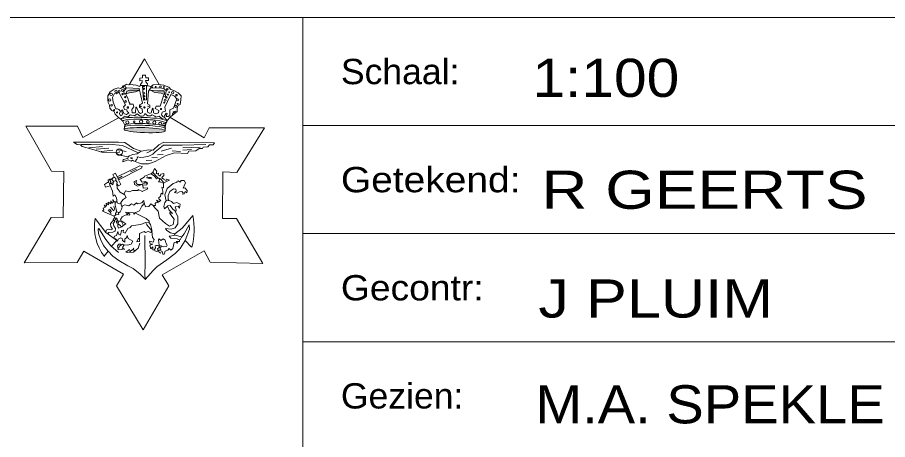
# Model space of a CAD drawing. Extents: x 295824 to 414724, y 24924 to 109024.
# Drawn here: x 402680 to 409522, y 29004 to 32324 of the extents above; entities that cross this region are included whole.
import ezdxf

# ---------------------------------------------------------------- set-up
doc = ezdxf.new("R2010")
doc.units = 0
doc.header["$LTSCALE"] = 100
doc.header["$PDMODE"] = 32
doc.header["$PDSIZE"] = 50
doc.layers.add('1', color=7, linetype='Continuous', lineweight=13)
doc.layers.add('3', color=7, linetype='Continuous')

msp = doc.modelspace()

# ---------------------------------------------------------------- hatches: boundary and pattern name
at = {"layer": '1'}
for points in [[(403531.6, 31722.8), (403540.6, 31743.8), (403560.6, 31751.8), (403641.6, 31751.8), (403609.6, 31737.8), (403557.6, 31731.8)], [(403720.6, 31751.8), (403780.6, 31745.8), (403834.6, 31745.8), (403837.6, 31716.8), (403809.6, 31727.8), (403760.6, 31733.8), (403725.6, 31750.8)]]:
    msp.add_hatch(color=256, dxfattribs=at).paths.add_polyline_path(points)
h = msp.add_hatch(color=256, dxfattribs=at)
edge = h.paths.add_edge_path()
edge.add_ellipse((403681.3, 31437.6), major_axis=(161, -5), ratio=0.122443, start_angle=0, end_angle=360)

# ---------------------------------------------------------------- linework, layer by layer
for p, q in [((395823.6, 32323.8), (413723.6, 32323.8)), ((404923.6, 32323.8), (404923.6, 28923.8)), ((403696.6, 31787.8), (403649.6, 31787.8)), ((403662.6, 31785.8), (403672.6, 31673.8)), ((403475.6, 31533.8), (403195.6, 31378.8)), ((403494.6, 31523.8), (403508.6, 31507.8)), ((403857.6, 31507.8), (403849.6, 31493.8)), ((403877.6, 31538.8), (404148.6, 31377.8)), ((404923.6, 31473.8), (413723.6, 31473.8)), ((403520.6, 31443.8), (403522.6, 31463.8)), ((403841.6, 31432.8), (403841.6, 31453.8)), ((403180.6, 31324.8), (403259.6, 31324.8)), ((403242.6, 31298.8), (403348.6, 31308.8)), ((403300.6, 31288.8), (403398.6, 31294.8)), ((403338.6, 31269.8), (403431.6, 31279.8)), ((403471.6, 31282.8), (403536.6, 31269.8)), ((403506.6, 31317.8), (403628.6, 31257.8)), ((403811.6, 31271.8), (403890.6, 31295.8)), ((403896.6, 31275.8), (403961.6, 31268.8)), ((403976.6, 31319.8), (404161.6, 31325.8)), ((403979.6, 31297.8), (404117.6, 31304.8)), ((403980.6, 31279.8), (404049.6, 31285.8)), ((403453.6, 31258.8), (403481.6, 31264.8)), ((403693.6, 31199.8), (403737.6, 31200.8)), ((403737.6, 31222.8), (403781.6, 31219.8)), ((403781.6, 31243.8), (403825.6, 31244.8)), ((403466.6, 31069.8), (403474.6, 31046.8)), ((403473.6, 31057.8), (403503.6, 31074.8)), ((403568.6, 31108.8), (403615.6, 31129.8)), ((403391.6, 31027.8), (403410.6, 31016.8)), ((403412.6, 31018.8), (403432.6, 31026.8)), ((403679.6, 31024.8), (403696.6, 31017.8)), ((403394.6, 30811.8), (403417.6, 30781.8)), ((403404.6, 30816.8), (403420.6, 30797.8)), ((403412.6, 30830.8), (403437.6, 30801.8)), ((403439.6, 30839.8), (403445.6, 30808.8)), ((403914.6, 30613.8), (403967.6, 30598.8)), ((404923.6, 30623.8), (413723.6, 30623.8)), ((403522.6, 30498.8), (403507.6, 30512.8)), ((403588.6, 30498.8), (403594.6, 30509.8)), ((404923.6, 29773.8), (413723.6, 29773.8))]:
    msp.add_line(p, q, dxfattribs=at)
for points in [[(403557.6, 31794.8), (403678.6, 31996.8), (403795.6, 31795.8)], [(403493.6, 31524.8), (403475.6, 31536.8), (403449.6, 31562.8), (403441.6, 31584.8), (403423.6, 31592.8), (403407.6, 31610.8), (403404.6, 31632.8), (403394.6, 31653.8), (403390.6, 31675.8), (403391.6, 31707.8), (403408.6, 31737.8), (403441.6, 31760.8), (403472.6, 31768.8), (403489.6, 31763.8), (403504.6, 31771.8), (403512.6, 31786.8), (403524.6, 31787.8), (403538.6, 31798.8), (403556.6, 31793.8), (403585.6, 31796.8), (403595.6, 31789.8), (403606.6, 31792.8), (403642.6, 31780.8), (403647.6, 31796.8), (403660.6, 31814.8), (403660.6, 31826.8), (403641.6, 31825.8), (403642.6, 31846.8), (403663.6, 31847.8), (403663.6, 31869.8), (403687.6, 31869.8), (403690.6, 31849.8), (403709.6, 31848.8), (403709.6, 31827.8), (403687.6, 31827.8), (403689.6, 31816.8), (403703.6, 31801.8), (403704.6, 31786.8), (403732.6, 31781.8), (403747.6, 31793.8)], [(403608.6, 31575.8), (403611.6, 31618.8), (403616.6, 31616.8), (403633.6, 31576.8), (403647.6, 31568.8), (403664.6, 31576.8), (403660.6, 31604.8), (403639.6, 31615.8), (403639.6, 31636.8), (403654.6, 31644.8), (403662.6, 31648.8), (403638.6, 31764.8), (403538.6, 31769.8), (403517.6, 31743.8), (403518.6, 31720.8), (403530.6, 31725.8), (403551.6, 31680.8), (403555.6, 31659.8), (403563.6, 31649.8), (403562.6, 31641.8), (403589.6, 31640.8), (403594.6, 31619.8), (403579.6, 31599.8), (403583.6, 31574.8), (403608.6, 31574.8)], [(403672.6, 31671.8), (403694.6, 31675.8), (403695.6, 31785.8), (403702.6, 31786.8)], [(403827.6, 31702.8), (403844.6, 31704.8), (403850.6, 31749.8), (403831.6, 31764.8), (403792.6, 31768.8), (403726.6, 31766.8), (403711.6, 31742.8), (403703.6, 31644.8), (403720.6, 31634.8), (403722.6, 31615.8), (403702.6, 31605.8), (403702.6, 31579.8), (403718.6, 31570.8)], [(403747.6, 31793.8), (403791.6, 31796.8), (403830.6, 31790.8)], [(403827.6, 31791.8), (403871.6, 31775.8), (403887.6, 31755.8), (403910.6, 31749.8), (403943.6, 31730.8), (403966.6, 31706.8), (403964.6, 31675.8), (403959.6, 31638.8), (403941.6, 31628.8), (403935.6, 31607.8), (403935.6, 31583.8), (403884.6, 31542.8), (403854.6, 31511.8)], [(403542.6, 31562.8), (403556.6, 31572.8), (403543.6, 31584.8), (403540.6, 31596.8), (403521.6, 31598.8), (403515.6, 31619.8), (403529.6, 31635.8), (403478.6, 31735.8), (403457.6, 31723.8), (403444.6, 31725.8), (403426.6, 31693.8), (403432.6, 31657.8), (403453.6, 31605.8), (403466.6, 31605.8), (403478.6, 31598.8), (403490.6, 31586.8), (403481.6, 31567.8), (403490.6, 31549.8), (403501.6, 31552.8), (403506.6, 31564.8), (403498.6, 31594.8), (403505.6, 31595.8), (403516.6, 31568.8), (403535.6, 31559.8), (403539.6, 31560.8)], [(403718.6, 31568.8), (403730.6, 31574.8), (403742.6, 31609.8), (403748.6, 31606.8), (403750.6, 31573.8), (403767.6, 31564.8), (403789.6, 31573.8), (403791.6, 31591.8), (403763.6, 31607.8), (403771.6, 31624.8), (403802.6, 31624.8), (403831.6, 31715.8)], [(403834.6, 31545.8), (403849.6, 31570.8), (403858.6, 31567.8), (403848.6, 31543.8), (403864.6, 31543.8), (403879.6, 31553.8), (403877.6, 31595.8), (403906.6, 31609.8), (403932.6, 31682.8), (403915.6, 31704.8), (403887.6, 31717.8), (403860.6, 31663.8), (403838.6, 31617.8), (403844.6, 31587.8), (403819.6, 31577.8), (403813.6, 31556.8), (403822.6, 31545.8), (403836.6, 31546.8)], [(403494.6, 31523.8), (403493.6, 31526.8), (403517.6, 31538.8), (403520.6, 31547.8), (403540.6, 31541.8), (403554.6, 31544.8), (403567.6, 31557.8), (403599.6, 31550.8), (403621.6, 31566.8), (403646.6, 31547.8), (403661.6, 31546.8), (403673.6, 31550.8), (403682.6, 31568.8), (403704.6, 31549.8), (403725.6, 31549.8), (403740.6, 31558.8), (403761.6, 31546.8), (403770.6, 31538.8), (403794.6, 31547.8), (403804.6, 31535.8), (403817.6, 31528.8), (403837.6, 31535.8), (403850.6, 31521.8), (403858.6, 31509.8)], [(403508.6, 31507.8), (403524.6, 31476.8), (403522.6, 31464.8)], [(403849.6, 31493.8), (403842.6, 31466.8), (403843.6, 31450.8)], [(403195.6, 31378.8), (403153.6, 31468.8), (402745.6, 31469.8), (402947.6, 31114.8), (403044.6, 31112.8), (403040.6, 30746.8), (402944.6, 30749.8), (402734.6, 30393.8), (403150.6, 30395.8), (403201.6, 30485.8), (403514.6, 30304.8), (403458.6, 30213.8), (403668.6, 29867.8), (403871.6, 30212.8), (403818.6, 30299.8), (404148.6, 30489.8), (404195.6, 30398.8), (404610.6, 30388.8), (404402.6, 30743.8), (404291.6, 30741.8), (404295.6, 31108.8), (404404.6, 31104.8), (404622.6, 31456.8), (404188.6, 31456.8), (404148.6, 31377.8)], [(403652.6, 31271.8), (403592.6, 31292.8), (403525.6, 31339.8), (403475.6, 31343.8), (403121.6, 31342.8), (403149.6, 31325.8), (403175.6, 31322.8), (403189.6, 31309.8), (403266.6, 31287.8), (403350.6, 31260.8), (403455.6, 31257.8), (403477.6, 31241.8), (403488.6, 31244.8), (403499.6, 31238.8), (403551.6, 31228.8), (403548.6, 31214.8), (403511.6, 31207.8), (403509.6, 31187.8), (403551.6, 31203.8)], [(403654.6, 31171.8), (403709.6, 31171.8), (403764.6, 31190.8), (403849.6, 31238.8), (403914.6, 31257.8), (404016.6, 31254.8), (404027.6, 31271.8), (404083.6, 31274.8), (404109.6, 31291.8), (404134.6, 31292.8), (404141.6, 31302.8), (404178.6, 31306.8), (404191.6, 31321.8), (404220.6, 31322.8), (404228.6, 31338.8), (403830.6, 31341.8), (403791.6, 31321.8), (403748.6, 31279.8), (403714.6, 31281.8), (403652.6, 31271.8), (403622.6, 31251.8), (403588.6, 31244.8), (403562.6, 31234.8), (403549.6, 31228.8)], [(403259.6, 31324.8), (403398.6, 31326.8), (403506.6, 31317.8)], [(403698.6, 31258.8), (403716.6, 31265.8), (403739.6, 31280.8)], [(403764.6, 31266.8), (403829.6, 31319.8), (403976.6, 31319.8)], [(403551.6, 31203.8), (403575.6, 31193.8), (403584.6, 31200.8), (403592.6, 31194.8), (403631.6, 31180.8), (403654.6, 31171.8)], [(403568.6, 31222.8), (403586.6, 31217.8), (403577.6, 31214.8), (403569.6, 31220.8)], [(403607.6, 31195.8), (403618.6, 31208.8), (403624.6, 31218.8), (403621.6, 31226.8), (403649.6, 31222.8), (403673.6, 31223.8), (403712.6, 31233.8), (403744.6, 31249.8), (403764.6, 31266.8)], [(403493.6, 30861.8), (403483.6, 30856.8), (403464.6, 30866.8), (403459.6, 30905.8), (403446.6, 30928.8), (403432.6, 30917.8), (403426.6, 30957.8), (403408.6, 31000.8), (403372.6, 30989.8), (403365.6, 31008.8), (403395.6, 31031.8), (403394.6, 31043.8), (403406.6, 31050.8), (403427.6, 31056.8), (403432.6, 31063.8), (403441.6, 31066.8), (403431.6, 31089.8), (403450.6, 31098.8), (403465.6, 31070.8), (403642.6, 31155.8), (403660.6, 31152.8), (403654.6, 31137.8), (403474.6, 31046.8), (403493.6, 31010.8), (403474.6, 30999.8), (403462.6, 31014.8), (403464.6, 31027.8), (403454.6, 31040.8), (403454.6, 31057.8), (403440.6, 31068.8)], [(403661.6, 30955.8), (403705.6, 30974.8), (403700.6, 30984.8), (403669.6, 30981.8), (403665.6, 31005.8), (403697.6, 31007.8), (403702.6, 31021.8), (403688.6, 31033.8), (403660.6, 31027.8), (403644.6, 31048.8), (403677.6, 31066.8), (403679.6, 31076.8), (403733.6, 31097.8), (403747.6, 31109.8), (403757.6, 31134.8), (403775.6, 31113.8), (403771.6, 31097.8), (403779.6, 31096.8), (403790.6, 31099.8), (403787.6, 31084.8), (403801.6, 31074.8), (403806.6, 31090.8), (403830.6, 31097.8), (403832.6, 31079.8), (403814.6, 31064.8), (403820.6, 31056.8), (403832.6, 31054.8), (403832.6, 31048.8), (403848.6, 31041.8), (403855.6, 31052.8), (403876.6, 31043.8), (403851.6, 31032.8), (403827.6, 31020.8), (403827.6, 30998.8), (403827.6, 30984.8), (403814.6, 30987.8), (403824.6, 30957.8), (403823.6, 30933.8), (403810.6, 30941.8), (403804.6, 30915.8)], [(403701.6, 31069.8), (403713.6, 31063.8), (403730.6, 31064.8), (403730.6, 31055.8), (403717.6, 31056.8), (403697.6, 31062.8), (403700.6, 31070.8)], [(403732.6, 31094.8), (403757.6, 31074.8), (403773.6, 31053.8), (403792.6, 31058.8), (403800.6, 31049.8), (403790.6, 31029.8), (403801.6, 31029.8), (403825.6, 31020.8)], [(403745.6, 31103.8), (403782.6, 31063.8), (403804.6, 31053.8), (403826.6, 31031.8), (403827.6, 31024.8)], [(403453.6, 31041.8), (403436.6, 31033.8), (403430.6, 31007.8), (403415.6, 31020.8), (403403.6, 31014.8), (403409.6, 31001.8)], [(403410.6, 31019.8), (403415.6, 31030.8), (403405.6, 31043.8), (403422.6, 31051.8), (403434.6, 31034.8)], [(403519.6, 30930.8), (403488.6, 30949.8), (403464.6, 30980.8), (403462.6, 31014.8)], [(403667.6, 31003.8), (403658.6, 31008.8), (403623.6, 30997.8), (403599.6, 31008.8), (403597.6, 31033.8), (403619.6, 31041.8), (403612.6, 31026.8), (403623.6, 31009.8), (403653.6, 31010.8), (403679.6, 31019.8), (403676.6, 31029.8)], [(403871.6, 30883.8), (403849.6, 30880.8), (403839.6, 30928.8), (403857.6, 30979.8), (403903.6, 31017.8), (403935.6, 31027.8), (403933.6, 31034.8), (403943.6, 31038.8), (403959.6, 31027.8), (403965.6, 31035.8), (403964.6, 31041.8), (403990.6, 31041.8), (404001.6, 31023.8), (403992.6, 31000.8), (403982.6, 30980.8), (403995.6, 30982.8), (404015.6, 30963.8), (404012.6, 30944.8), (403998.6, 30954.8), (403990.6, 30937.8), (403977.6, 30932.8), (403982.6, 30943.8), (403973.6, 30954.8), (403954.6, 30952.8), (403935.6, 30941.8), (403916.6, 30947.8), (403929.6, 30958.8), (403924.6, 30973.8), (403907.6, 30975.8), (403878.6, 30954.8), (403864.6, 30922.8), (403865.6, 30891.8), (403870.6, 30883.8)], [(403804.6, 30915.8), (403792.6, 30908.8), (403791.6, 30897.8), (403799.6, 30888.8), (403808.6, 30886.8), (403794.6, 30874.8), (403787.6, 30877.8), (403774.6, 30887.8), (403782.6, 30876.8), (403786.6, 30865.8), (403771.6, 30867.8), (403762.6, 30859.8), (403766.6, 30845.8), (403747.6, 30844.8), (403728.6, 30858.8), (403714.6, 30837.8), (403688.6, 30833.8), (403676.6, 30862.8), (403674.6, 30884.8), (403658.6, 30866.8), (403625.6, 30858.8), (403617.6, 30865.8), (403594.6, 30846.8), (403576.6, 30856.8), (403555.6, 30841.8), (403525.6, 30849.8), (403497.6, 30839.8), (403493.6, 30869.8), (403512.6, 30892.8), (403534.6, 30906.8), (403520.6, 30935.8), (403529.6, 30960.8), (403561.6, 30951.8), (403585.6, 30962.8), (403617.6, 30961.8), (403628.6, 30963.8), (403628.6, 30970.8), (403663.6, 30955.8)], [(403461.6, 30794.8), (403447.6, 30848.8), (403449.6, 30867.8), (403458.6, 30874.8), (403441.6, 30874.8), (403431.6, 30890.8), (403433.6, 30871.8), (403425.6, 30863.8), (403413.6, 30881.8), (403415.6, 30856.8), (403394.6, 30871.8), (403396.6, 30850.8), (403377.6, 30863.8), (403379.6, 30840.8), (403363.6, 30848.8), (403373.6, 30831.8), (403353.6, 30823.8), (403360.6, 30810.8), (403348.6, 30800.8), (403367.6, 30793.8), (403441.6, 30760.8)], [(403531.6, 30701.8), (403509.6, 30683.8), (403500.6, 30676.8), (403475.6, 30666.8), (403470.6, 30678.8), (403469.6, 30701.8), (403491.6, 30687.8), (403493.6, 30680.8), (403506.6, 30682.8), (403512.6, 30693.8), (403491.6, 30735.8), (403502.6, 30755.8), (403528.6, 30769.8), (403548.6, 30772.8), (403560.6, 30767.8), (403563.6, 30775.8), (403554.6, 30785.8), (403541.6, 30773.8), (403540.6, 30789.8), (403526.6, 30793.8), (403592.6, 30786.8), (403598.6, 30774.8), (403602.6, 30789.8), (403616.6, 30793.8), (403640.6, 30803.8), (403657.6, 30840.8), (403678.6, 30863.8)], [(403748.6, 30844.8), (403759.6, 30827.8), (403785.6, 30799.8), (403797.6, 30745.8), (403844.6, 30703.8), (403875.6, 30682.8), (403904.6, 30694.8), (403913.6, 30737.8), (403877.6, 30780.8), (403877.6, 30790.8), (403898.6, 30780.8), (403874.6, 30807.8), (403861.6, 30840.8), (403836.6, 30818.8), (403832.6, 30836.8), (403839.6, 30869.8), (403850.6, 30881.8)], [(403872.6, 30884.8), (403892.6, 30875.8), (403908.6, 30860.8), (403934.6, 30867.8), (403959.6, 30855.8), (403955.6, 30824.8), (403944.6, 30838.8), (403921.6, 30833.8), (403928.6, 30809.8), (403924.6, 30796.8), (403901.6, 30814.8), (403880.6, 30845.8), (403860.6, 30841.8)], [(403506.6, 30841.8), (403498.6, 30815.8), (403488.6, 30795.8), (403475.6, 30785.8), (403478.6, 30774.8), (403454.6, 30771.8), (403441.6, 30761.8), (403442.6, 30747.8), (403445.6, 30744.8), (403437.6, 30744.8), (403433.6, 30732.8), (403437.6, 30728.8), (403427.6, 30722.8), (403411.6, 30699.8), (403414.6, 30678.8), (403426.6, 30658.8), (403416.6, 30653.8), (403397.6, 30658.8), (403377.6, 30649.8), (403375.6, 30632.8), (403392.6, 30623.8), (403399.6, 30632.8), (403429.6, 30635.8), (403449.6, 30643.8), (403451.6, 30662.8), (403439.6, 30685.8), (403433.6, 30703.8), (403443.6, 30717.8), (403444.6, 30727.8), (403452.6, 30733.8), (403459.6, 30740.8), (403446.6, 30748.8), (403461.6, 30744.8), (403466.6, 30726.8), (403456.6, 30719.8), (403465.6, 30705.8), (403474.6, 30708.8), (403468.6, 30721.8), (403501.6, 30720.8), (403531.6, 30701.8)], [(403477.6, 30788.8), (403460.6, 30795.8), (403450.6, 30781.8), (403452.6, 30773.8)], [(403922.6, 30794.8), (403942.6, 30754.8), (403942.6, 30699.8), (403921.6, 30669.8), (403889.6, 30659.8), (403844.6, 30664.8), (403855.6, 30648.8), (403882.6, 30629.8), (403917.6, 30622.8), (403975.6, 30666.8), (404034.6, 30736.8), (404058.6, 30765.8)], [(403416.6, 30522.8), (403462.6, 30570.8), (403374.6, 30632.8), (403292.6, 30741.8)], [(403603.6, 30787.8), (403644.6, 30766.8), (403692.6, 30741.8), (403715.6, 30722.8), (403716.6, 30708.8), (403687.6, 30711.8), (403649.6, 30696.8), (403591.6, 30688.8), (403576.6, 30685.8), (403567.6, 30671.8)], [(403475.6, 30475.8), (403413.6, 30526.8), (403375.6, 30576.8), (403319.6, 30664.8), (403315.6, 30659.8), (403316.6, 30623.8), (403334.6, 30580.8), (403357.6, 30530.8), (403390.6, 30488.8)], [(403567.6, 30672.8), (403547.6, 30662.8), (403528.6, 30627.8), (403512.6, 30634.8), (403513.6, 30651.8), (403498.6, 30647.8), (403489.6, 30612.8), (403474.6, 30619.8), (403470.6, 30639.8), (403460.6, 30609.8), (403442.6, 30602.8), (403438.6, 30586.8), (403450.6, 30583.8), (403466.6, 30564.8), (403471.6, 30580.8), (403492.6, 30590.8), (403502.6, 30585.8), (403506.6, 30569.8), (403524.6, 30556.8), (403524.6, 30581.8), (403537.6, 30591.8), (403543.6, 30609.8), (403550.6, 30585.8), (403586.6, 30564.8), (403575.6, 30540.8), (403545.6, 30532.8), (403520.6, 30535.8), (403506.6, 30514.8)], [(403689.6, 30709.8), (403698.6, 30691.8), (403737.6, 30644.8), (403728.6, 30632.8), (403707.6, 30641.8), (403688.6, 30633.8), (403676.6, 30640.8), (403640.6, 30624.8), (403639.6, 30590.8), (403639.6, 30561.8), (403618.6, 30559.8), (403631.6, 30586.8)], [(403715.6, 30708.8), (403726.6, 30694.8), (403733.6, 30664.8), (403738.6, 30643.8)], [(404049.6, 30516.8), (403999.6, 30569.8), (404032.6, 30659.8), (404029.6, 30692.8), (403990.6, 30622.8), (403969.6, 30594.8), (403958.6, 30574.8)], [(403999.6, 30569.8), (403960.6, 30506.8), (403921.6, 30467.8), (403855.6, 30418.8), (403777.6, 30361.8), (403748.6, 30332.8), (403684.6, 30263.8), (403682.6, 30308.8), (403684.6, 30379.8), (403682.6, 30607.8)], [(403753.6, 30492.8), (403744.6, 30496.8), (403745.6, 30518.8), (403729.6, 30503.8), (403720.6, 30531.8), (403745.6, 30539.8), (403723.6, 30542.8), (403718.6, 30564.8), (403746.6, 30557.8), (403756.6, 30576.8), (403742.6, 30593.8), (403737.6, 30643.8)], [(403917.6, 30621.8), (403915.6, 30616.8), (403912.6, 30608.8), (403872.6, 30603.8), (403887.6, 30587.8), (403935.6, 30582.8), (403953.6, 30573.8), (403953.6, 30562.8), (403929.6, 30561.8), (403940.6, 30548.8), (403912.6, 30552.8), (403902.6, 30506.8), (403887.6, 30492.8), (403872.6, 30505.8), (403863.6, 30492.8), (403842.6, 30486.8), (403833.6, 30462.8), (403822.6, 30462.8), (403819.6, 30483.8), (403811.6, 30481.8), (403804.6, 30470.8), (403794.6, 30475.8), (403789.6, 30494.8), (403810.6, 30494.8), (403800.6, 30511.8), (403793.6, 30513.8), (403782.6, 30503.8), (403786.6, 30490.8), (403775.6, 30482.8), (403760.6, 30489.8), (403758.6, 30497.8), (403766.6, 30512.8)], [(403766.6, 30511.8), (403763.6, 30526.8), (403770.6, 30530.8), (403780.6, 30529.8), (403793.6, 30531.8), (403788.6, 30574.8), (403795.6, 30583.8), (403806.6, 30568.8), (403826.6, 30583.8), (403841.6, 30572.8), (403847.6, 30550.8), (403858.6, 30533.8), (403853.6, 30522.8), (403829.6, 30519.8), (403811.6, 30527.8), (403796.6, 30527.8), (403791.6, 30519.8), (403808.6, 30515.8), (403810.6, 30522.8)], [(403492.6, 30539.8), (403477.6, 30540.8), (403466.6, 30527.8), (403471.6, 30502.8)], [(403475.6, 30508.8), (403485.6, 30528.8), (403505.6, 30539.8), (403515.6, 30535.8)], [(403641.6, 30548.8), (403628.6, 30509.8), (403593.6, 30476.8), (403564.6, 30474.8), (403566.6, 30483.8), (403582.6, 30495.8), (403592.6, 30496.8), (403600.6, 30490.8)], [(403362.6, 30447.8), (403393.6, 30484.8), (403429.6, 30447.8), (403476.6, 30411.8), (403547.6, 30371.8), (403589.6, 30350.8), (403644.6, 30305.8), (403686.6, 30261.8)], [(403511.6, 30505.8), (403501.6, 30497.8), (403480.6, 30502.8), (403470.6, 30495.8)], [(403560.6, 30480.8), (403548.6, 30474.8), (403532.6, 30477.8), (403561.6, 30499.8), (403564.6, 30491.8)]]:
    msp.add_lwpolyline(points, dxfattribs=at)
for points in [[(403531.6, 31722.8), (403540.6, 31743.8), (403560.6, 31751.8), (403641.6, 31751.8), (403609.6, 31737.8), (403557.6, 31731.8)], [(403720.6, 31751.8), (403780.6, 31745.8), (403834.6, 31745.8), (403837.6, 31716.8), (403809.6, 31727.8), (403760.6, 31733.8), (403725.6, 31750.8)]]:
    msp.add_lwpolyline(points, close=True, dxfattribs=at)
for centre, radius in [((403456.3, 31742.6), 9.06), ((403480.3, 31744.6), 8), ((403506.3, 31750.6), 8.54), ((403524.3, 31774.6), 9.22), ((403672.3, 31783.6), 6), ((403675.3, 31762.6), 5.39), ((403735.3, 31776.6), 7.28), ((403767.3, 31778.6), 3.16), ((403804.3, 31778.6), 7.28), ((403832.3, 31776.6), 3.16), ((403858.3, 31758.6), 6), ((403405.3, 31675.6), 9.22), ((403417.3, 31718.6), 9.49), ((403507.3, 31720.6), 5), ((403527.3, 31696.6), 5.39), ((403674.3, 31728.6), 7.81), ((403676.3, 31683.6), 4.47), ((403677.3, 31703.6), 5), ((403842.3, 31673.6), 8.06), ((403851.3, 31694.6), 6.08), ((403863.3, 31716.6), 4), ((403873.3, 31736.6), 3.16), ((403901.3, 31731.6), 9.06), ((403931.3, 31712.6), 6), ((403942.3, 31675.6), 8), ((403420.3, 31632.6), 6.32), ((403531.3, 31663.6), 7), ((403548.3, 31615.6), 6.08), ((403649.3, 31623.6), 4), ((403678.3, 31615.6), 5.39), ((403680.3, 31652.6), 1.41), ((403708.3, 31624.6), 1.41), ((403834.3, 31653.6), 4.12), ((403926.3, 31624.6), 8.25), ((403940.3, 31643.6), 4.12), ((403440.3, 31595.6), 4), ((403463.3, 31576.6), 4.12), ((403809.3, 31603.6), 4.12), ((403903.3, 31563.6), 4.24), ((403907.3, 31578.6), 3), ((403920.3, 31580.6), 6.08), ((403544.3, 31498.6), 12), ((403597.3, 31502.6), 7.28), ((403652.3, 31504.6), 13.2), ((403706.3, 31502.6), 10.1), ((403757.3, 31497.6), 12), ((403803.3, 31488.6), 10.8), ((403832.3, 31482.6), 8.54)]:
    msp.add_circle(centre, radius, dxfattribs=at)
for centre, radius, start, end in [((403659.3, 30673.6), 373.3, 169.49737, 218.03161), ((403573.1, 30656.6), 497.4, 343.65538, 12.66423)]:
    msp.add_arc(centre, radius, start, end, dxfattribs=at)
for centre, major_axis, ratio in [((403675.3, 31515.1), (182, -7.5), 0.12032), ((403679.3, 31499.6), (171, -8), 0.131533), ((403682.8, 31457.1), (160.5, -6.5), 0.111744), ((403683.8, 31470.6), (159.5, -6), 0.111275)]:
    msp.add_ellipse(centre, major_axis=major_axis, ratio=ratio, start_param=6.283185, end_param=9.424778, dxfattribs=at)
msp.add_ellipse((403681.3, 31437.6), major_axis=(161, -5), ratio=0.122443, dxfattribs=at)
msp.add_point((403481.6, 31264.8), dxfattribs=at)

# ---------------------------------------------------------------- texts
for s, width, p in [('Schaal:', 1.05, (405223.6, 31798.8)), ('Getekend:', 1.15, (405223.6, 30948.8)), ('Gecontr:', 1.1, (405223.6, 30098.8)), ('Gezien:', 1.05, (405223.6, 29248.8))]:
    msp.add_text(s, height=199, dxfattribs=dict(at, width=width)).set_placement(p)
at = {"layer": '3'}
for s, width, p in [('1:100            ', 1.15, (406729.6, 31698.8)), ('R GEERTS         ', 1.25, (406800.6, 30818.8)), ('J PLUIM          ', 1.2, (406776.6, 29963.8)), ('M.A. SPEKLE      ', 1.1, (406752.6, 29131.8))]:
    msp.add_text(s, height=300, dxfattribs=dict(at, width=width)).set_placement(p)

doc.saveas('drawing.dxf')
